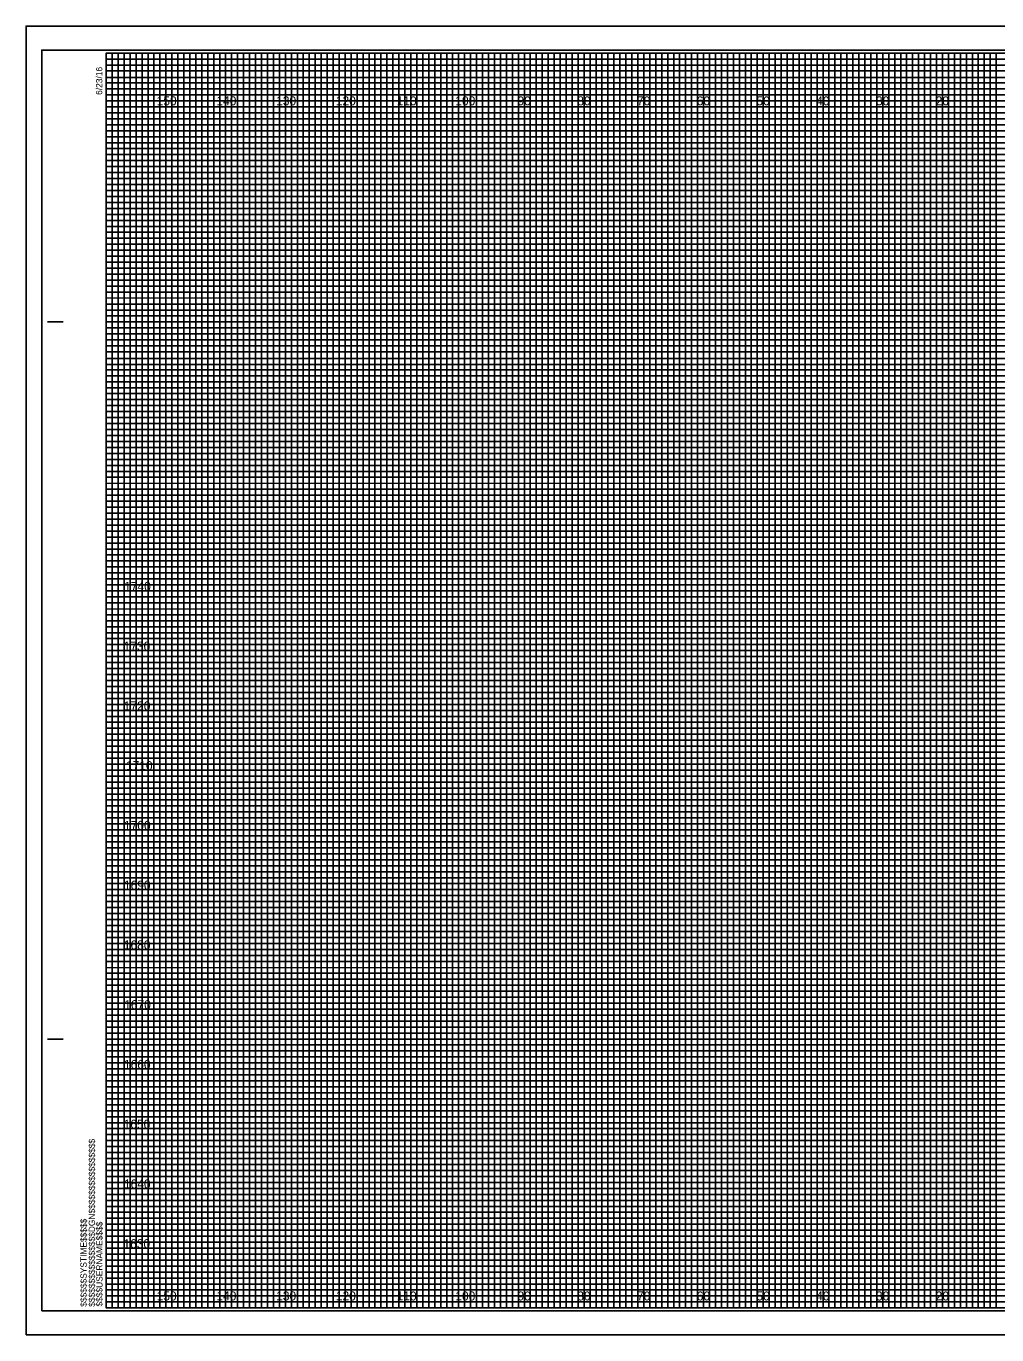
# Model space of a CAD drawing. Extents: x -3334 to 0, y 84 to 12624.
# Drawn here: x -336.5 to -174, y 744.2 to 963.2 of the extents above; entities that cross this region are included whole.
import ezdxf

# ---------------------------------------------------------------- set-up
doc = ezdxf.new("R2010")
doc.units = 0
for name, color, linetype in [('Old_Level_62', 7, 'Continuous'), ('Pattern 1', 7, 'Continuous'), ('Pattern 18', 7, 'Continuous'), ('Pattern 4', 7, 'Continuous'), ('Pattern 5', 7, 'Continuous'), ('Prop Dimension', 7, 'Continuous'), ('Prop Horizontal Alignment', 7, 'Continuous'), ('Raster_Level_0', 7, 'Continuous'), ('Scratch_Level_0', 7, 'Continuous'), ('Scratch_Level_3', 7, 'Continuous'), ('Scratch_Level_5', 7, 'Continuous')]:
    doc.layers.add(name, color=color, linetype=linetype)

msp = doc.modelspace()

# ---------------------------------------------------------------- linework, layer by layer
at = {"layer": 'Old_Level_62'}
for p, q in [((-332.92, 913.67), (-330.42, 913.67)), ((-332.82, 913.67), (-330.32, 913.67)), ((-332.92, 793.67), (-330.42, 793.67)), ((-332.82, 793.67), (-330.32, 793.67)), ((-323.12, 748.67), (-323.12, 748.67)), ((-323.12, 748.67), (-323.12, 748.67)), ((-323.12, 748.67), (-323.12, 748.67)), ((-323.12, 748.67), (-323.12, 748.67)), ((-323.12, 748.67), (-323.12, 748.67)), ((-323.12, 748.67), (-323.12, 748.67)), ((-323.12, 748.67), (-323.12, 748.67))]:
    msp.add_line(p, q, dxfattribs=at)
msp.add_lwpolyline([(-3.12, 958.67), (-323.12, 958.67), (-323.12, 748.67), (-3.12, 748.67)], close=True, dxfattribs=at)
at = {"layer": 'Pattern 18'}
msp.add_lwpolyline([(-336.52, 744.17), (0.18, 744.17), (0.18, 963.17), (-336.52, 963.17)], close=True, dxfattribs=at)
at = {"layer": 'Pattern 4'}
for p, q in [((-323.12, 957.67), (-63.12, 957.67)), ((-63.12, 956.65), (-323.12, 956.65)), ((-323.12, 956.65), (-323.12, 955.67)), ((-323.12, 955.67), (-63.12, 955.67)), ((-63.12, 954.56), (-323.12, 954.56)), ((-323.12, 954.56), (-323.12, 952.67)), ((-323.12, 952.67), (-3.12, 952.67))]:
    msp.add_line(p, q, dxfattribs=at)
for points in [[(-323.12, 951.67), (-53.12, 951.67), (-3.12, 951.67), (-3.12, 950.67), (-323.12, 950.67)], [(-323.12, 949.67), (-3.12, 949.67), (-3.12, 947.67), (-323.12, 947.67)], [(-323.12, 946.67), (-3.12, 946.67), (-3.12, 945.67), (-323.12, 945.65)], [(-323.12, 944.67), (-3.12, 944.67), (-3.12, 942.67), (-323.12, 942.67)], [(-323.12, 941.67), (-3.12, 941.67), (-3.12, 940.67), (-323.12, 940.67)], [(-323.12, 939.67), (-3.12, 939.67), (-3.12, 937.67), (-323.12, 937.67)], [(-323.12, 936.67), (-3.12, 936.67), (-3.12, 935.67), (-323.12, 935.67)], [(-323.12, 934.67), (-3.12, 934.67), (-3.12, 932.67), (-323.12, 932.67)], [(-323.12, 931.67), (-3.12, 931.67), (-3.12, 930.67), (-323.12, 930.67)], [(-323.12, 929.67), (-3.12, 929.67), (-3.12, 927.67), (-323.12, 927.67)], [(-323.12, 926.67), (-3.12, 926.67), (-3.12, 925.67), (-323.12, 925.67)], [(-323.12, 924.67), (-3.12, 924.67), (-3.12, 922.62), (-3.12, 921.67), (-3.12, 920.67), (-323.12, 920.67)], [(-323.12, 922.67), (-3.12, 922.67), (-3.12, 921.67), (-323.12, 921.67)], [(-323.12, 919.67), (-3.12, 919.67), (-3.12, 917.67), (-323.12, 917.7)], [(-323.12, 917.7), (-3.12, 917.67), (-3.12, 916.67), (-323.12, 916.67)], [(-323.12, 915.67), (-3.12, 915.67), (-3.12, 914.67), (-323.12, 914.67)], [(-323.12, 912.67), (-3.12, 912.67), (-3.12, 911.67), (-323.12, 911.67)], [(-323.12, 910.67), (-3.12, 910.67), (-3.12, 909.67), (-323.12, 909.67)], [(-323.19, 907.56), (-3.12, 907.56), (-3.12, 906.55), (-323.19, 906.55)], [(-323.12, 905.67), (-3.12, 905.67), (-3.12, 904.67), (-323.12, 904.67)], [(-323.12, 902.67), (-3.12, 902.67), (-3.12, 901.67), (-323.12, 901.67)], [(-323.12, 900.67), (-3.12, 900.67), (-3.12, 899.67), (-323.12, 899.67)], [(-323.12, 897.67), (-3.12, 897.67), (-3.12, 896.67), (-323.12, 896.67)], [(-323.12, 895.67), (-3.12, 895.67), (-3.12, 894.67), (-323.12, 894.67)], [(-323.12, 892.67), (-3.12, 892.67), (-3.12, 891.67), (-323.12, 891.67)], [(-323.12, 890.67), (-3.12, 890.67), (-3.12, 889.67), (-323.12, 889.67)], [(-323.12, 887.67), (-3.12, 887.67), (-3.13, 886.65), (-323.12, 886.67)], [(-323.12, 885.67), (-3.12, 885.67), (-3.12, 884.67), (-323.12, 884.67)], [(-323.12, 882.67), (-3.12, 882.67), (-3.12, 881.67), (-323.12, 881.67)], [(-323.12, 880.67), (-3.12, 880.67), (-3.12, 879.67), (-323.12, 879.67)], [(-323.12, 877.67), (-3.12, 877.67), (-3.12, 876.67), (-323.12, 876.67)], [(-323.12, 875.67), (-3.12, 875.67), (-3.12, 874.67), (-323.12, 874.67)], [(-323.12, 872.67), (-3.12, 872.67), (-3.12, 871.67), (-323.12, 871.67)], [(-323.12, 870.67), (-3.12, 870.67), (-3.12, 869.67), (-323.12, 869.67)], [(-323.12, 867.67), (-3.12, 867.67), (-3.12, 866.67), (-323.12, 866.67)], [(-323.12, 865.66), (-3.05, 865.58), (-3.12, 864.67), (-323.12, 864.67)], [(-323.12, 862.67), (-3.12, 862.67), (-3.12, 861.67), (-323.12, 861.67)], [(-323.12, 860.67), (-3.12, 860.67), (-3.12, 859.67), (-323.12, 859.67)], [(-323.12, 857.67), (-3.12, 857.67), (-3.12, 856.67), (-323.12, 856.67)], [(-323.12, 855.67), (-3.12, 855.67), (-3.12, 854.67), (-323.12, 854.67)], [(-323.12, 852.67), (-3.12, 852.67), (-3.12, 851.67), (-323.12, 851.67)], [(-323.12, 850.67), (-3.12, 850.67), (-3.12, 849.67), (-323.12, 849.67)], [(-323.12, 847.67), (-3.12, 847.67), (-3.12, 846.67), (-323.12, 846.67)], [(-323.12, 845.67), (-3.12, 845.67), (-3.12, 844.67), (-323.12, 844.67)], [(-323.12, 842.67), (-3.12, 842.67), (-3.12, 841.67), (-323.12, 841.67)], [(-323.12, 840.67), (-3.12, 840.67), (-3.12, 839.67), (-323.12, 839.67)], [(-323.12, 837.67), (-3.12, 837.67), (-3.12, 836.67), (-323.12, 836.67)], [(-323.12, 835.67), (-3.12, 835.67), (-3.12, 834.67), (-323.12, 834.67)], [(-323.12, 832.67), (-3.12, 832.67), (-3.12, 831.67), (-323.12, 831.67)], [(-323.12, 830.67), (-3.12, 830.67), (-3.12, 829.67), (-323.12, 829.67)], [(-323.12, 827.67), (-3.12, 827.67), (-3.13, 826.65), (-323.12, 826.67)], [(-323.12, 825.67), (-3.12, 825.67), (-3.12, 824.67), (-323.12, 824.67)], [(-323.12, 822.67), (-3.12, 822.67), (-3.12, 821.67), (-323.12, 821.67)], [(-323.12, 820.67), (-3.12, 820.67), (-3.12, 819.67), (-323.12, 819.67)], [(-323.12, 817.67), (-3.12, 817.67), (-3.12, 816.67), (-323.12, 816.67)], [(-323.12, 815.67), (-3.12, 815.67), (-3.12, 814.67), (-323.12, 814.67)], [(-323.12, 812.67), (-3.12, 812.67), (-3.12, 811.67), (-323.12, 811.67)], [(-323.12, 810.67), (-3.12, 810.67), (-3.12, 809.67), (-323.12, 809.67)], [(-323.12, 807.67), (-3.12, 807.67), (-3.12, 806.67), (-323.12, 806.67)], [(-323.12, 805.66), (-3.05, 805.58), (-3.12, 804.67), (-323.12, 804.67)], [(-323.12, 802.67), (-3.12, 802.67), (-3.12, 801.67), (-323.12, 801.67)], [(-323.12, 800.67), (-3.12, 800.67), (-3.12, 799.67), (-323.12, 799.67)], [(-323.12, 797.67), (-3.12, 797.67), (-3.12, 796.67), (-323.12, 796.67)], [(-323.12, 795.67), (-3.12, 795.67), (-3.12, 794.67), (-323.12, 794.67)], [(-323.12, 792.67), (-3.12, 792.67), (-3.12, 791.67), (-323.12, 791.67)], [(-323.12, 790.67), (-3.12, 790.67), (-3.12, 789.67), (-323.12, 789.67)], [(-323.12, 787.67), (-3.12, 787.67), (-3.12, 786.67), (-323.12, 786.67)], [(-323.12, 785.67), (-3.12, 785.67), (-3.12, 784.67), (-323.12, 784.67)], [(-323.12, 782.67), (-3.12, 782.67), (-3.12, 781.67), (-323.12, 781.67)], [(-323.12, 780.67), (-3.12, 780.67), (-3.12, 779.67), (-323.12, 779.67)], [(-323.12, 777.67), (-3.12, 777.67), (-3.12, 776.67), (-323.12, 776.67)], [(-323.12, 775.67), (-3.12, 775.67), (-3.12, 774.67), (-323.12, 774.67)], [(-323.12, 772.67), (-3.12, 772.67), (-3.12, 771.67), (-323.12, 771.67)], [(-323.12, 770.67), (-3.12, 770.67), (-3.12, 769.67), (-323.12, 769.67)], [(-323.12, 767.67), (-3.12, 767.67), (-3.12, 766.67), (-323.12, 766.67)], [(-323.12, 765.67), (-3.12, 765.67), (-3.12, 764.67), (-323.12, 764.67)], [(-323.12, 762.67), (-3.12, 762.67), (-3.12, 761.67), (-323.12, 761.67)], [(-323.12, 760.67), (-3.12, 760.67), (-3.12, 759.67), (-323.12, 759.67)], [(-323.12, 757.67), (-3.12, 757.67), (-3.12, 756.67), (-323.12, 756.67)], [(-323.12, 755.67), (-3.12, 755.67), (-3.12, 754.67), (-323.12, 754.67)], [(-323.12, 752.67), (-3.12, 752.67), (-3.12, 751.67), (-323.12, 751.67)], [(-323.12, 750.67), (-3.12, 750.67), (-3.12, 749.67), (-323.12, 749.67)]]:
    msp.add_lwpolyline(points, dxfattribs=at)
at = {"layer": 'Pattern 5'}
for p, q in [((0.18, 963.17), (-336.52, 963.17)), ((-336.52, 963.17), (-336.52, 744.17)), ((-336.52, 744.17), (0.18, 744.17))]:
    msp.add_line(p, q, dxfattribs=at)
at = {"layer": 'Prop Dimension'}
for points in [[(-323.12, 748.67), (-322.12, 748.67), (-322.12, 958.67), (-321.12, 958.67), (-321.12, 748.67)], [(-321.12, 748.67), (-320.12, 748.67), (-320.12, 958.67), (-319.12, 958.67), (-319.12, 748.67)], [(-318.12, 748.67), (-317.12, 748.67), (-317.12, 958.67), (-316.12, 958.67), (-316.12, 748.67)], [(-316.12, 748.67), (-315.12, 748.67), (-315.12, 958.67), (-314.12, 958.67), (-314.12, 748.67)], [(-313.12, 748.67), (-312.12, 748.67), (-312.12, 958.67), (-311.12, 958.67), (-311.12, 748.67)], [(-311.12, 748.67), (-310.12, 748.67), (-310.12, 958.67), (-309.12, 958.67), (-309.12, 748.67)], [(-308.12, 748.67), (-307.12, 748.67), (-307.12, 958.67), (-306.12, 958.67), (-306.12, 748.67)], [(-306.12, 748.67), (-305.12, 748.67), (-305.12, 958.67), (-304.12, 958.67), (-304.12, 748.67)], [(-303.12, 748.67), (-302.12, 748.67), (-302.12, 958.67), (-301.12, 958.67), (-301.12, 748.67)], [(-301.12, 748.67), (-300.12, 748.67), (-300.12, 958.67), (-299.12, 958.67), (-299.12, 748.67)], [(-298.12, 748.67), (-297.12, 748.67), (-297.12, 958.67), (-296.12, 958.67), (-296.12, 748.67)], [(-296.12, 748.67), (-295.12, 748.67), (-295.12, 958.67), (-294.12, 958.67), (-294.12, 748.67)], [(-293.12, 748.67), (-292.12, 748.67), (-292.12, 958.67), (-291.12, 958.67), (-291.12, 748.67)], [(-291.12, 748.67), (-290.12, 748.67), (-290.12, 958.67), (-289.12, 958.67), (-289.12, 748.67)], [(-288.12, 748.67), (-287.12, 748.67), (-287.12, 958.67), (-286.12, 958.67), (-286.12, 748.67)], [(-286.12, 748.67), (-285.12, 748.67), (-285.12, 958.67), (-284.12, 958.67), (-284.12, 748.67)], [(-283.12, 748.67), (-282.12, 748.67), (-282.12, 958.67), (-281.12, 958.67), (-281.12, 748.67)], [(-281.12, 748.67), (-280.12, 748.67), (-280.12, 958.67), (-279.12, 958.67), (-279.12, 748.67)], [(-278.12, 748.67), (-277.12, 748.67), (-277.12, 958.67), (-276.12, 958.67), (-276.12, 748.67)], [(-276.12, 748.67), (-275.12, 748.67), (-275.12, 958.67), (-274.12, 958.67), (-274.12, 748.67)], [(-273.12, 748.67), (-272.12, 748.67), (-272.12, 958.67), (-271.12, 958.67), (-271.12, 748.67)], [(-271.12, 748.67), (-270.12, 748.67), (-270.12, 958.67), (-269.12, 958.67), (-269.12, 748.67)], [(-268.12, 748.67), (-267.12, 748.67), (-267.12, 958.67), (-266.12, 958.67), (-266.12, 748.67)], [(-266.12, 748.67), (-265.12, 748.67), (-265.12, 958.67), (-264.12, 958.67), (-264.12, 748.67)], [(-263.12, 748.67), (-262.12, 748.67), (-262.12, 958.67), (-261.12, 958.67), (-261.12, 748.67)], [(-261.12, 748.67), (-260.12, 748.67), (-260.12, 958.67), (-259.12, 958.67), (-259.12, 748.67)], [(-258.12, 748.67), (-257.12, 748.67), (-257.12, 958.67), (-256.12, 958.67), (-256.12, 748.67)], [(-256.12, 748.67), (-255.12, 748.67), (-255.12, 958.67), (-254.12, 958.67), (-254.12, 748.67)], [(-253.12, 748.67), (-252.12, 748.67), (-252.12, 958.67), (-251.12, 958.67), (-251.12, 748.67)], [(-251.12, 748.67), (-250.12, 748.67), (-250.12, 958.67), (-249.12, 958.67), (-249.12, 748.67)], [(-248.12, 748.67), (-247.12, 748.67), (-247.12, 958.67), (-246.12, 958.67), (-246.12, 748.67)], [(-246.12, 748.67), (-245.12, 748.67), (-245.12, 958.67), (-244.12, 958.67), (-244.12, 748.67)], [(-243.12, 748.67), (-242.12, 748.67), (-242.12, 958.67), (-241.12, 958.67), (-241.12, 748.67)], [(-241.12, 748.67), (-240.12, 748.67), (-240.12, 958.67), (-239.12, 958.67), (-239.12, 748.67)], [(-238.12, 748.67), (-237.12, 748.67), (-237.12, 958.67), (-236.12, 958.67), (-236.12, 748.67)], [(-236.12, 748.67), (-235.12, 748.67), (-235.12, 958.67), (-234.12, 958.67), (-234.12, 748.67)], [(-233.12, 748.67), (-232.12, 748.67), (-232.12, 958.67), (-231.12, 958.67), (-231.12, 748.67)], [(-231.12, 748.67), (-230.12, 748.67), (-230.12, 958.67), (-229.12, 958.67), (-229.12, 748.67)], [(-228.12, 748.67), (-227.12, 748.67), (-227.12, 958.67), (-226.12, 958.67), (-226.12, 748.67)], [(-226.12, 748.67), (-225.12, 748.67), (-225.12, 958.67), (-224.12, 958.67), (-224.12, 748.67)], [(-223.12, 748.67), (-222.12, 748.67), (-222.12, 958.67), (-221.12, 958.67), (-221.12, 748.67)], [(-221.12, 748.67), (-220.12, 748.67), (-220.12, 958.67), (-219.12, 958.67), (-219.12, 748.67)], [(-218.12, 748.67), (-217.12, 748.67), (-217.12, 958.67), (-216.12, 958.67), (-216.12, 748.67)], [(-216.12, 748.67), (-215.12, 748.67), (-215.12, 958.67), (-214.12, 958.67), (-214.12, 748.67)], [(-213.12, 748.67), (-212.12, 748.67), (-212.12, 958.67), (-211.12, 958.67), (-211.12, 748.67)], [(-211.12, 748.67), (-210.12, 748.67), (-210.12, 958.67), (-209.12, 958.67), (-209.12, 748.67)], [(-208.12, 748.67), (-207.12, 748.67), (-207.12, 958.67), (-206.12, 958.67), (-206.12, 748.67)], [(-206.12, 748.67), (-205.12, 748.67), (-205.12, 958.67), (-204.12, 958.67), (-204.12, 748.67)], [(-203.12, 748.67), (-202.12, 748.67), (-202.12, 958.67), (-201.12, 958.67), (-201.12, 748.67)], [(-201.12, 748.67), (-200.12, 748.67), (-200.12, 958.67), (-199.12, 958.67), (-199.12, 748.67)], [(-198.12, 748.67), (-197.12, 748.67), (-197.12, 958.67), (-196.12, 958.67), (-196.12, 748.67)], [(-196.12, 748.67), (-195.12, 748.67), (-195.12, 958.67), (-194.12, 958.67), (-194.12, 748.67)], [(-193.12, 748.67), (-192.12, 748.67), (-192.12, 958.67), (-191.12, 958.67), (-191.12, 748.67)], [(-191.12, 748.67), (-190.12, 748.67), (-190.12, 958.67), (-189.12, 958.67), (-189.12, 748.67)], [(-188.12, 748.67), (-187.12, 748.67), (-187.12, 958.67), (-186.12, 958.67), (-186.12, 748.67)], [(-186.12, 748.67), (-185.12, 748.67), (-185.12, 958.67), (-184.12, 958.67), (-184.12, 748.67)], [(-183.12, 748.67), (-182.12, 748.67), (-182.12, 958.67), (-181.12, 958.67), (-181.12, 748.67)], [(-181.12, 748.67), (-180.12, 748.67), (-180.12, 958.67), (-179.12, 958.67), (-179.12, 748.67)], [(-178.12, 748.67), (-177.12, 748.67), (-177.12, 958.67), (-176.12, 958.67), (-176.12, 748.67)], [(-176.12, 748.67), (-175.12, 748.67), (-175.12, 958.67), (-174.12, 958.67), (-174.12, 748.67)]]:
    msp.add_lwpolyline(points, dxfattribs=at)
at = {"layer": 'Prop Horizontal Alignment'}
for points in [[(-323.12, 958.67), (-318.12, 958.67), (-318.12, 748.67), (-308.12, 748.67), (-308.12, 958.67), (-298.12, 958.67), (-298.12, 748.67), (-288.12, 748.67), (-288.12, 958.67), (-278.12, 958.67), (-278.12, 748.67), (-268.12, 748.67), (-268.12, 958.67), (-258.12, 958.67), (-258.12, 748.67), (-248.12, 748.67), (-248.12, 958.67), (-238.12, 958.67), (-238.12, 748.67), (-228.12, 748.67), (-228.12, 958.67), (-218.12, 958.67), (-218.12, 748.67), (-208.12, 748.67), (-208.12, 958.67), (-198.12, 958.67), (-198.12, 748.67), (-188.12, 748.67), (-188.12, 958.67), (-178.12, 958.67), (-178.12, 748.67), (-168.12, 748.67)], [(-323.12, 953.67), (-48.12, 953.67)], [(-323.12, 933.67), (-3.12, 933.67), (-3.12, 943.67), (-323.12, 943.67)], [(-323.12, 913.67), (-3.12, 913.67), (-3.12, 923.67), (-323.12, 923.67)], [(-323.12, 893.67), (-3.12, 893.67), (-3.12, 903.67), (-323.12, 903.67)], [(-323.12, 873.67), (-3.12, 873.67), (-3.12, 883.67), (-323.12, 883.67)], [(-323.12, 853.67), (-3.12, 853.67), (-3.12, 863.67), (-323.12, 863.67)], [(-323.12, 833.67), (-3.12, 833.67), (-3.12, 843.67), (-323.12, 843.67)], [(-323.12, 813.67), (-3.12, 813.67), (-3.12, 823.67), (-323.12, 823.67)], [(-323.12, 793.67), (-3.12, 793.67), (-3.12, 803.67), (-323.12, 803.67)], [(-323.12, 773.67), (-3.12, 773.67), (-3.12, 783.67), (-323.12, 783.67)], [(-323.12, 753.67), (-3.12, 753.67), (-3.12, 763.67), (-323.12, 763.67)]]:
    msp.add_lwpolyline(points, dxfattribs=at)
at = {"layer": 'Scratch_Level_0'}
for p, q in [((-313.12, 748.67), (-313.12, 958.67)), ((-303.12, 748.67), (-303.12, 958.67)), ((-293.12, 748.67), (-293.12, 958.67)), ((-283.12, 748.67), (-283.12, 958.67)), ((-273.12, 748.67), (-273.12, 958.67)), ((-263.12, 748.67), (-263.12, 958.67)), ((-253.12, 748.67), (-253.12, 958.67)), ((-243.12, 748.67), (-243.12, 958.67)), ((-233.12, 748.67), (-233.12, 958.67)), ((-223.12, 748.67), (-223.12, 958.67)), ((-213.12, 748.67), (-213.12, 958.67)), ((-203.12, 748.67), (-203.12, 958.67)), ((-193.12, 748.67), (-193.12, 958.67)), ((-183.12, 748.67), (-183.12, 958.67)), ((-323.12, 948.67), (-3.12, 948.67)), ((-323.12, 938.67), (-3.12, 938.67)), ((-323.12, 928.67), (-3.12, 928.67)), ((-323.12, 918.67), (-3.12, 918.67)), ((-323.12, 908.67), (-3.12, 908.67)), ((-323.12, 898.67), (-3.12, 898.67)), ((-323.12, 888.67), (-3.12, 888.67)), ((-323.12, 878.67), (-3.12, 878.67)), ((-323.12, 868.67), (-3.12, 868.67)), ((-323.12, 858.67), (-3.12, 858.67)), ((-323.12, 848.67), (-3.12, 848.67)), ((-323.12, 838.67), (-3.12, 838.67)), ((-323.12, 828.67), (-3.12, 828.67)), ((-323.12, 818.67), (-3.12, 818.67)), ((-323.12, 808.67), (-3.12, 808.67)), ((-323.12, 798.67), (-3.12, 798.67)), ((-323.12, 788.67), (-3.12, 788.67)), ((-323.12, 778.67), (-3.12, 778.67)), ((-323.12, 768.67), (-3.12, 768.67)), ((-323.12, 758.67), (-3.12, 758.67))]:
    msp.add_line(p, q, dxfattribs=at)
at = {"layer": 'Scratch_Level_3'}
for p, q in [((-313.12, 958.67), (-323.12, 958.67)), ((-313.12, 748.67), (-313.12, 958.67)), ((-293.12, 958.67), (-303.12, 958.67)), ((-303.12, 958.67), (-303.12, 748.67)), ((-293.12, 748.67), (-293.12, 958.67)), ((-273.12, 958.67), (-283.12, 958.67)), ((-283.12, 958.67), (-283.12, 748.67)), ((-273.12, 748.67), (-273.12, 958.67)), ((-253.12, 958.67), (-263.12, 958.67)), ((-263.12, 958.67), (-263.12, 748.67)), ((-253.12, 748.67), (-253.12, 958.67)), ((-233.12, 958.67), (-243.12, 958.67)), ((-243.12, 958.67), (-243.12, 748.67)), ((-233.12, 748.67), (-233.12, 958.67)), ((-213.12, 958.67), (-223.12, 958.67)), ((-223.12, 958.67), (-223.12, 748.67)), ((-213.12, 748.67), (-213.12, 958.67)), ((-193.12, 958.67), (-203.12, 958.67)), ((-203.12, 958.67), (-203.12, 748.67)), ((-193.12, 748.67), (-193.12, 958.67)), ((-173.12, 958.67), (-183.12, 958.67)), ((-183.12, 958.67), (-183.12, 748.67)), ((-303.12, 748.67), (-313.12, 748.67)), ((-283.12, 748.67), (-293.12, 748.67)), ((-263.12, 748.67), (-273.12, 748.67)), ((-243.12, 748.67), (-253.12, 748.67)), ((-223.12, 748.67), (-233.12, 748.67)), ((-203.12, 748.67), (-213.12, 748.67)), ((-183.12, 748.67), (-193.12, 748.67))]:
    msp.add_line(p, q, dxfattribs=at)
for points in [[(-323.12, 948.67), (-3.12, 948.67), (-3.12, 938.67), (-323.12, 938.67)], [(-323.12, 928.67), (-3.12, 928.67), (-3.12, 918.67), (-323.12, 918.67)], [(-323.12, 908.67), (-3.12, 908.67), (-3.12, 898.67), (-323.12, 898.67)], [(-323.12, 888.67), (-3.12, 888.67), (-3.12, 878.67), (-323.12, 878.67)], [(-323.12, 868.67), (-3.12, 868.67), (-3.12, 858.67), (-323.12, 858.67)], [(-323.12, 848.67), (-3.12, 848.67), (-3.12, 838.67), (-323.12, 838.67)], [(-323.12, 828.67), (-3.12, 828.67), (-3.12, 818.67), (-323.12, 818.67)], [(-323.12, 808.67), (-3.12, 808.67), (-3.12, 798.67), (-323.12, 798.67)], [(-323.12, 788.67), (-3.12, 788.67), (-3.12, 778.67), (-323.12, 778.67)], [(-323.12, 768.67), (-3.12, 768.67), (-3.12, 758.67), (-323.12, 758.67)]]:
    msp.add_lwpolyline(points, dxfattribs=at)
at = {"layer": 'Scratch_Level_5'}
msp.add_lwpolyline([(-333.92, 748.17), (-0.72, 748.17), (-0.72, 959.17), (-333.92, 959.17)], close=True, dxfattribs=at)

# ---------------------------------------------------------------- texts
at = {"layer": 'Old_Level_62'}
for s, p in [('6/23/16', (-323.77, 951.67)), ('$$$$$$$$$$$$$$$$DGN$$$$$$$$$$$$$$$$', (-325, 748.85)), ('$$$$$$SYSTIME$$$$$', (-326.38, 748.85)), ('$$$$USERNAME$$$$', (-323.74, 748.9))]:
    msp.add_text(s, height=1.05, rotation=90, dxfattribs=at).set_placement(p)
at = {"layer": 'Pattern 1'}
for s, p in [('1740', (-320.11, 868.67)), ('1730', (-320.2, 858.67)), ('1720', (-320.18, 848.67)), ('1710', (-319.81, 838.67)), ('1700', (-320.14, 828.67)), ('1690', (-320.15, 818.67)), ('1680', (-320.17, 808.67)), ('1670', (-320.11, 798.67)), ('1660', (-320.15, 788.67)), ('1650', (-320.2, 778.67)), ('1640', (-320.15, 768.67)), ('1630', (-320.23, 758.67))]:
    msp.add_text(s, height=1.5, dxfattribs=at).set_placement(p)
at = {"layer": 'Raster_Level_0'}
for s, p in [('150', (-314.67, 949.92)), ('140', (-304.67, 949.92)), ('130', (-294.67, 949.92)), ('120', (-284.67, 949.92)), ('110', (-274.49, 949.92)), ('100', (-264.67, 949.92)), ('90', (-254.26, 949.92)), ('80', (-244.26, 949.92)), ('70', (-234.26, 949.92)), ('60', (-224.26, 949.92)), ('50', (-214.26, 949.92)), ('40', (-204.26, 949.92)), ('30', (-194.26, 949.92)), ('20', (-184.26, 949.92)), ('150', (-314.67, 749.92)), ('140', (-304.67, 749.92)), ('130', (-294.67, 749.92)), ('120', (-284.67, 749.92)), ('110', (-274.49, 749.92)), ('100', (-264.67, 749.92)), ('90', (-254.26, 749.92)), ('80', (-244.26, 749.92)), ('70', (-234.26, 749.92)), ('60', (-224.26, 749.92)), ('50', (-214.26, 749.92)), ('40', (-204.26, 749.92)), ('30', (-194.26, 749.92)), ('20', (-184.26, 749.92))]:
    msp.add_text(s, height=1.5, dxfattribs=at).set_placement(p)

doc.saveas('drawing.dxf')
